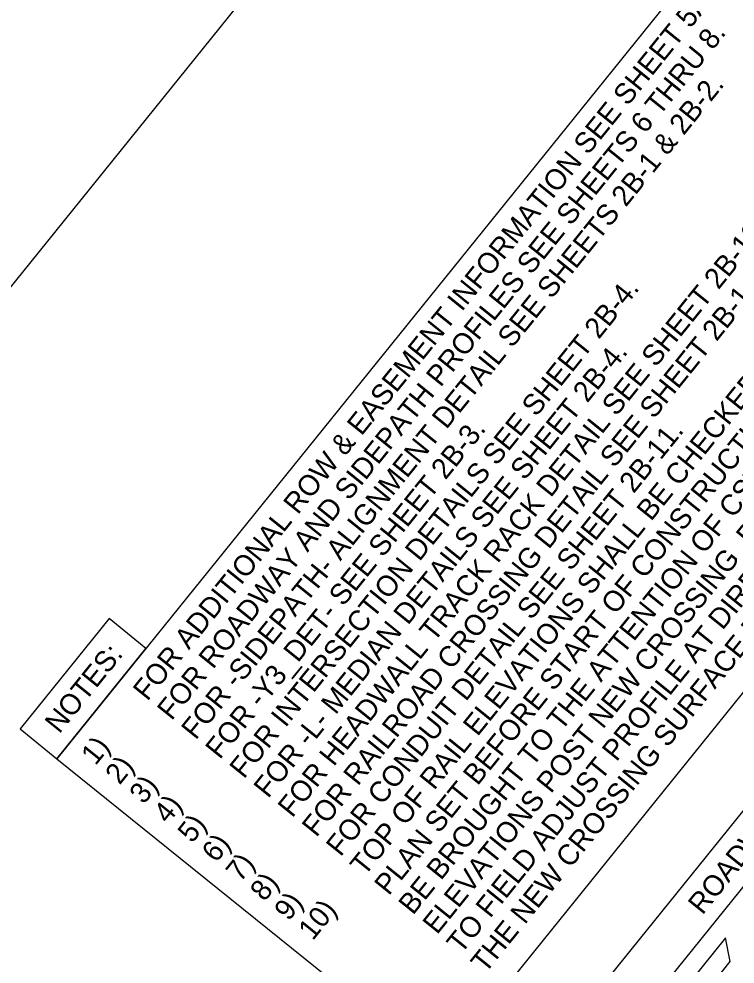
# Model space of a CAD drawing. Extents: x 1487832 to 1490056, y 498345 to 500343.
# Drawn here: x 1489387.8 to 1489582.6, y 499474.1 to 499731.4 of the extents above; entities that cross this region are included whole.
import ezdxf

# ---------------------------------------------------------------- set-up
doc = ezdxf.new("R2010")
doc.units = 0
for name, color, linetype in [('Prop Grid Mask', 7, 'Continuous'), ('Prop Horizontal Alignment Curve and Spiral Data', 7, 'Continuous'), ('Sheet Block Title CELL', 7, 'Continuous')]:
    doc.layers.add(name, color=color, linetype=linetype)

msp = doc.modelspace()

# ---------------------------------------------------------------- linework, layer by layer
at = {"layer": 'Prop Grid Mask'}
for points in [[(1489252.37, 499708.83), (1489421.93, 499919.09), (1489527.15, 499834.24), (1489357.58, 499623.98)], [(1489502.46, 499445.87), (1489705.45, 499697.58), (1489601.09, 499781.75), (1489398.1, 499530.03)], [(1489528.31, 499425.02), (1489667.7, 499597.86), (1489657.54, 499606.05), (1489518.16, 499433.21)], [(1489528.31, 499425.02), (1489667.7, 499597.86), (1489692.57, 499577.8), (1489553.18, 499404.96)], [(1489398.1, 499530.03), (1489422.32, 499560.06), (1489412.28, 499568.16), (1489388.06, 499538.13)]]:
    msp.add_lwpolyline(points, close=True, dxfattribs=at)
at = {"layer": 'Sheet Block Title CELL'}
msp.add_lwpolyline([(1489528.31, 499425.02), (1489667.7, 499597.86), (1489692.57, 499577.8), (1489553.18, 499404.96)], close=True, dxfattribs=at)
msp.add_lwpolyline([(1489589.89, 499458.51), (1489576.72, 499469.13), (1489581.3, 499474.8), (1489580.02, 499481.24), (1489565.02, 499462.65), (1489568.94, 499459.49), (1489573.56, 499465.21), (1489586.73, 499454.59), (1489589.89, 499458.51)], dxfattribs=at)

# ---------------------------------------------------------------- texts
at = {"layer": 'Prop Horizontal Alignment Curve and Spiral Data'}
for s, p in [('FOR ADDITIONAL ROW & EASEMENT INFORMATION SEE SHEET 5A.', (1489422.72, 499545.5)), ('FOR ROADWAY AND SIDEPATH PROFILES SEE SHEETS 6 THRU 8.', (1489429.29, 499540.2)), ('FOR -SIDEPATH- ALIGNMENT DETAIL SEE SHEETS 2B-1 & 2B-2.', (1489435.86, 499534.91)), ('PLAN SET BEFORE START OF CONSTRUCTION. ANY DISCREPANCIES SHALL', (1489488.4, 499492.53)), ('TOP OF RAIL ELEVATIONS SHALL BE CHECKED AND VERIFIED TO MATCH', (1489481.83, 499497.83)), ('ELEVATIONS POST NEW CROSSING  PANEL INSTALLATION.  CONTRACTOR', (1489501.53, 499481.94)), ('BE BROUGHT TO THE ATTENTION OF CSX.  FIELD VERIFY TOP OF RAIL', (1489494.97, 499487.24)), ('FOR RAILROAD CROSSING DETAIL SEE SHEET 2B-14 & 2B-15.', (1489468.69, 499508.42)), ('TO FIELD ADJUST PROFILE AT DIRECTION OF ENGINEER AT TIE-INS TO', (1489508.1, 499476.64)), ('THE NEW CROSSING SURFACE PANEL AS THE ELEVATION MAY CHANGE.', (1489514.67, 499471.35)), ('FOR HEADWALL TRACK RACK DETAIL SEE SHEET 2B-12.', (1489462.13, 499513.72)), ('FOR INTERSECTION DETAILS SEE SHEET 2B-4.', (1489448.99, 499524.31)), ('FOR -L- MEDIAN DETAILS SEE SHEET 2B-4.', (1489455.56, 499519.02)), ('FOR -Y3_DET- SEE SHEET 2B-3.', (1489442.42, 499529.61)), ('FOR CONDUIT DETAIL SEE SHEET 2B-11.', (1489475.26, 499503.13)), ('NOTES:', (1489398.75, 499536.62)), ('ROADWAY DESIGN', (1489573.75, 499487.28)), ('1)', (1489408.6, 499527.98)), ('2)', (1489415.16, 499522.69)), ('3)', (1489421.73, 499517.39)), ('4)', (1489428.3, 499512.09)), ('5)', (1489434.87, 499506.8)), ('6)', (1489441.43, 499501.5)), ('7)', (1489448, 499496.2)), ('8)', (1489454.57, 499490.91)), ('9)', (1489461.14, 499485.61)), ('10)', (1489467.71, 499480.31))]:
    msp.add_text(s, height=5.625, rotation=51.1156, dxfattribs=at).set_placement(p)

doc.saveas('drawing.dxf')
